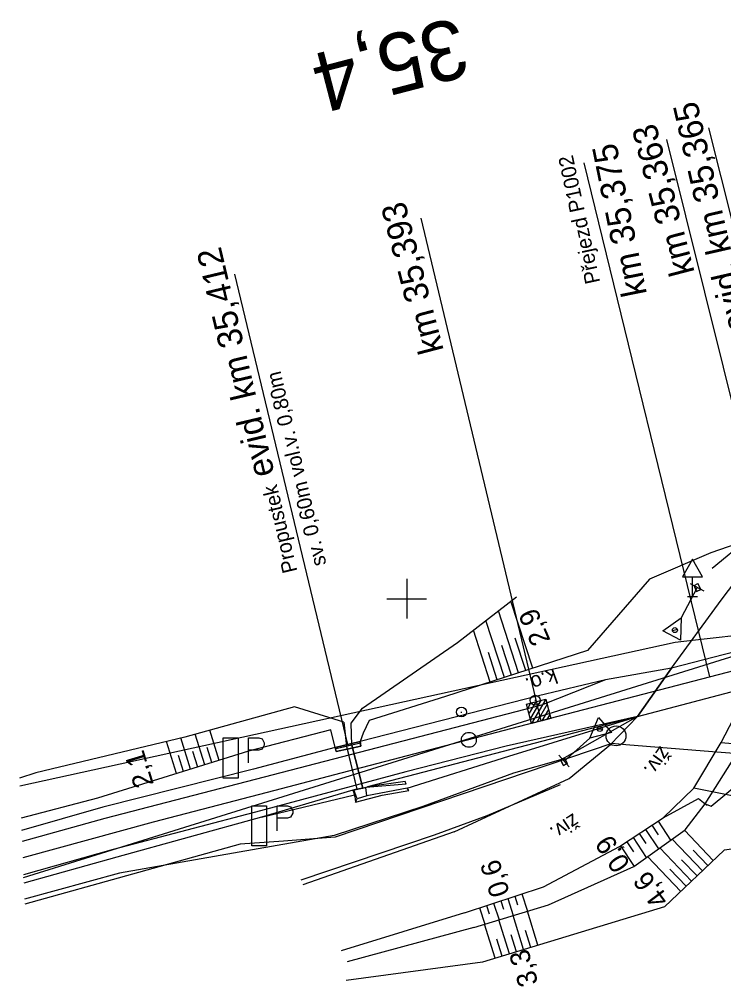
# Model space of a CAD drawing. Extents: x -806456 to -805395, y -1150847 to -1150506.
# Drawn here: x -806239 to -806168.1, y -1150739 to -1150641.7 of the extents above; entities that cross this region are included whole.
import ezdxf

# ---------------------------------------------------------------- set-up
doc = ezdxf.new("R2010")
doc.units = 0
for name, color, linetype in [('0381KM032-037P - Vrstva 1', 7, 'Continuous'), ('0381KM032-037P - Vrstva 12', 7, 'Continuous'), ('0381KM032-037P - Vrstva 13', 7, 'Continuous'), ('0381KM032-037P - Vrstva 16', 7, 'Continuous'), ('0381KM032-037P - Vrstva 17', 7, 'Continuous'), ('0381KM032-037P - Vrstva 19', 7, 'Continuous'), ('0381KM032-037P - Vrstva 27', 7, 'Continuous'), ('0381KM032-037P - Vrstva 3', 7, 'Continuous'), ('0381KM032-037P - Vrstva 36', 7, 'Continuous'), ('0381KM032-037P - Vrstva 4', 7, 'Continuous'), ('0381KM032-037P - Vrstva 43', 7, 'Continuous'), ('0381KM032-037P - Vrstva 48', 7, 'Continuous'), ('0381KM032-037P - Vrstva 49', 7, 'Continuous'), ('0381KM032-037P - Vrstva 51', 7, 'Continuous'), ('0381KM032-037P - Vrstva 7', 7, 'Continuous'), ('hran DP - hran DP', 7, 'Continuous'), ('krizky_1000 - Vrstva 1', 7, 'Continuous'), ('vyt_sit - polygon', 7, 'Continuous')]:
    doc.layers.add(name, color=color, linetype=linetype)

msp = doc.modelspace()

# ---------------------------------------------------------------- linework, layer by layer
at = {"layer": '0381KM032-037P - Vrstva 1'}
for points in [[(-805989.76, -1150661.17), (-806027.03, -1150670.9), (-806064.32, -1150680.56), (-806101.67, -1150690.24), (-806138.44, -1150699.75), (-806158.28, -1150704.94), (-806163.64, -1150706.34), (-806175.38, -1150709.4), (-806186.46, -1150712.29), (-806205.201, -1150717.188), (-806213.26, -1150719.29)], [(-806213.26, -1150719.29), (-806225.487, -1150722.48), (-806238.622, -1150726.073)]]:
    msp.add_lwpolyline(points, dxfattribs=at)
at = {"layer": '0381KM032-037P - Vrstva 12'}
for p, q in [((-806171.097, -1150698.685), (-806170.698, -1150698.477)), ((-806170.424, -1150699.073), (-806170.42, -1150699.072)), ((-806184.517, -1150716.193), (-806184.135, -1150716.013)), ((-806184.236, -1150716.767), (-806184.232, -1150716.767)), ((-806183.852, -1150716.584), (-806183.846, -1150716.582))]:
    msp.add_line(p, q, dxfattribs=at)
for points in [[(-806171.096, -1150698.684), (-806170.697, -1150698.478), (-806170.42, -1150699.072), (-806170.837, -1150699.265), (-806171.096, -1150698.684), (-806171.097, -1150698.685), (-806170.836, -1150699.265), (-806170.837, -1150699.265)], [(-806170.836, -1150699.265), (-806170.424, -1150699.073), (-806170.698, -1150698.477), (-806170.697, -1150698.478)], [(-806184.517, -1150716.196), (-806184.136, -1150716.011), (-806183.846, -1150716.582), (-806184.232, -1150716.767), (-806184.517, -1150716.196), (-806184.517, -1150716.193), (-806184.236, -1150716.767), (-806183.852, -1150716.584), (-806184.135, -1150716.013), (-806184.136, -1150716.011)]]:
    msp.add_lwpolyline(points, dxfattribs=at)
at = {"layer": '0381KM032-037P - Vrstva 13'}
for p, q in [((-806200.065, -1150718.644), (-806204.115, -1150718.971)), ((-806204.115, -1150718.971), (-806203.948, -1150718.928)), ((-806203.996, -1150719.808), (-806204.115, -1150718.971)), ((-806200.148, -1150718.382), (-806203.948, -1150718.928)), ((-806200.065, -1150718.644), (-806200.148, -1150718.382)), ((-806204.985, -1150720.124), (-806205.321, -1150719.23)), ((-806203.996, -1150719.808), (-806204.985, -1150720.124))]:
    msp.add_line(p, q, dxfattribs=at)
for points in [[(-806204.115, -1150718.971), (-806204.42, -1150719.04), (-806205.012, -1150719.152), (-806205.321, -1150719.23)], [(-806205.147, -1150720.463), (-806202.482, -1150719.745), (-806199.79, -1150719.277), (-806199.947, -1150719.038), (-806203.996, -1150719.808)], [(-806205.415, -1150719.241), (-806205.341, -1150719.246), (-806205.321, -1150719.23)], [(-806205.415, -1150719.241), (-806205.331, -1150719.519), (-806205.259, -1150719.74), (-806205.211, -1150719.896), (-806205.18, -1150720.145), (-806205.147, -1150720.463), (-806204.985, -1150720.124)]]:
    msp.add_lwpolyline(points, dxfattribs=at)
at = {"layer": '0381KM032-037P - Vrstva 16'}
msp.add_lwpolyline([(-806166.069, -1150720.047), (-806171.128, -1150719.056), (-806168.37, -1150714.464), (-806166.085, -1150714.657), (-806164.602, -1150713.817)], dxfattribs=at)
at = {"layer": '0381KM032-037P - Vrstva 17'}
msp.add_line((-806191.898, -1150721.811), (-806184.517, -1150718.669), dxfattribs=at)
for points in [[(-806169.284, -1150696.914), (-806165.684, -1150693.969), (-806155.413, -1150686.939), (-806141.029, -1150680.901), (-806121.846, -1150675.136), (-806106.33, -1150670.053), (-806095.392, -1150665.453)], [(-806210.617, -1150728.275), (-806197.196, -1150723.748), (-806191.898, -1150721.811)]]:
    msp.add_lwpolyline(points, dxfattribs=at)
at = {"layer": '0381KM032-037P - Vrstva 19'}
for p, q in [((-806157.446, -1150701.329), (-806169.593, -1150652.631)), ((-806205.929, -1150714.672), (-806217.278, -1150667.349)), ((-806169.987, -1150720.615), (-806157.733, -1150701.3)), ((-806204.679, -1150714.37), (-806207.178, -1150714.973)), ((-806206.05, -1150714.858), (-806207.127, -1150715.107)), ((-806207.086, -1150715.378), (-806207.127, -1150715.107)), ((-806206.05, -1150714.841), (-806205.013, -1150719.154)), ((-806206.05, -1150714.858), (-806205.012, -1150719.152)), ((-806205.518, -1150714.716), (-806205.523, -1150714.718)), ((-806204.418, -1150719.038), (-806205.523, -1150714.718)), ((-806205.518, -1150714.716), (-806204.42, -1150719.04)), ((-806204.606, -1150714.816), (-806204.652, -1150714.519)), ((-806205.013, -1150719.154), (-806204.418, -1150719.038)), ((-806170.188, -1150720.467), (-806169.786, -1150720.763))]:
    msp.add_line(p, q, dxfattribs=at)
for points in [[(-806204.682, -1150714.372), (-806204.679, -1150714.37), (-806204.652, -1150714.519), (-806207.127, -1150715.107), (-806207.178, -1150714.973), (-806207.177, -1150714.974)], [(-806204.682, -1150714.372), (-806204.606, -1150714.816), (-806207.086, -1150715.378), (-806207.177, -1150714.974), (-806204.682, -1150714.372)], [(-806205.523, -1150714.718), (-806206.05, -1150714.841), (-806206.05, -1150714.858)], [(-806204.652, -1150714.519), (-806205.518, -1150714.716)], [(-806205.341, -1150719.246), (-806203.948, -1150718.928)], [(-806204.418, -1150719.038), (-806204.42, -1150719.04), (-806204.115, -1150718.971), (-806203.948, -1150718.928)], [(-806205.012, -1150719.152), (-806205.321, -1150719.23), (-806205.341, -1150719.246)], [(-806205.013, -1150719.154), (-806205.012, -1150719.152)]]:
    msp.add_lwpolyline(points, dxfattribs=at)
at = {"layer": '0381KM032-037P - Vrstva 27'}
msp.add_line((-806187.119, -1150710.216), (-806187.019, -1150710.216), dxfattribs=at)
msp.add_circle((-806187.069, -1150710.216), 0.5, dxfattribs=at)
at = {"layer": '0381KM032-037P - Vrstva 3'}
for p, q in [((-806186.46, -1150712.29), (-806198.557, -1150661.727)), ((-806186.51, -1150710.236), (-806187.561, -1150712.03)), ((-806185.997, -1150710.102), (-806187.428, -1150712.542)), ((-806187.537, -1150710.504), (-806187.829, -1150711.003)), ((-806187.024, -1150710.37), (-806187.695, -1150711.516)), ((-806185.863, -1150710.615), (-806186.915, -1150712.409)), ((-806185.729, -1150711.129), (-806186.401, -1150712.275)), ((-806185.596, -1150711.642), (-806185.888, -1150712.141))]:
    msp.add_line(p, q, dxfattribs=at)
msp.add_lwpolyline([(-806158.28, -1150704.94), (-806161.571, -1150691.159), (-806164.309, -1150692.072), (-806173.835, -1150653.806)], dxfattribs=at)
msp.add_lwpolyline([(-806185.492, -1150712.038), (-806187.428, -1150712.542), (-806187.932, -1150710.607), (-806185.997, -1150710.102)], close=True, dxfattribs=at)
at = {"layer": '0381KM032-037P - Vrstva 36'}
for points in [[(-806218.444, -1150714.003), (-806216.955, -1150714.003), (-806216.955, -1150718.032), (-806218.444, -1150718.032)], [(-806215.575, -1150720.837), (-806214.086, -1150720.837), (-806214.086, -1150724.866), (-806215.575, -1150724.866)]]:
    msp.add_lwpolyline(points, close=True, dxfattribs=at)
for points in [[(-806215.911, -1150716.502), (-806215.911, -1150713.994)], [(-806215.911, -1150713.994), (-806214.868, -1150713.994)], [(-806214.868, -1150713.994), (-806214.552, -1150714.099), (-806214.331, -1150714.505), (-806214.331, -1150714.726), (-806214.552, -1150715.142), (-806214.868, -1150715.232)], [(-806214.868, -1150715.232), (-806215.911, -1150715.232)], [(-806213.042, -1150723.336), (-806213.042, -1150720.828)], [(-806213.042, -1150720.828), (-806211.999, -1150720.828)], [(-806211.999, -1150720.828), (-806211.683, -1150720.933), (-806211.462, -1150721.339), (-806211.462, -1150721.56), (-806211.683, -1150721.976), (-806211.999, -1150722.066)], [(-806211.999, -1150722.066), (-806213.042, -1150722.066)]]:
    msp.add_lwpolyline(points, dxfattribs=at)
at = {"layer": '0381KM032-037P - Vrstva 4'}
for p, q in [((-806169.501, -1150707.868), (-806182.162, -1150656.159)), ((-806170.089, -1150699.232), (-806171.461, -1150698.498)), ((-806172.782, -1150703.087), (-806173.251, -1150703.226)), ((-806176.794, -1150711.837), (-806203.948, -1150718.928)), ((-806180.805, -1150713.083), (-806180.317, -1150713.117)), ((-806184.68, -1150715.748), (-806183.652, -1150716.916))]:
    msp.add_line(p, q, dxfattribs=at)
for points in [[(-806170.775, -1150698.865), (-806172.404, -1150701.937), (-806172.472, -1150704.171), (-806174.24, -1150703.24), (-806172.404, -1150701.937)], [(-806173.358, -1150707), (-806179.992, -1150708.144), (-806186.437, -1150710.716), (-806215.256, -1150718.168), (-806230.349, -1150722.089), (-806238.693, -1150724.411)], [(-806179.992, -1150708.144), (-806186.747, -1150709.759), (-806204.682, -1150714.372)], [(-806176.794, -1150711.837), (-806190.006, -1150714.82), (-806200.085, -1150717.418), (-806214.718, -1150721.345), (-806229.528, -1150725.211), (-806238.55, -1150727.775)], [(-806184.166, -1150716.332), (-806181.562, -1150714.027), (-806180.714, -1150711.959), (-806179.386, -1150713.451), (-806181.562, -1150714.027)], [(-806207.177, -1150714.974), (-806215.394, -1150717.144), (-806230.58, -1150720.973), (-806238.74, -1150723.305)], [(-806207.177, -1150714.974), (-806207.086, -1150715.378), (-806204.606, -1150714.816), (-806204.682, -1150714.372)], [(-806205.415, -1150719.241), (-806205.341, -1150719.246), (-806203.948, -1150718.928)], [(-806205.415, -1150719.241), (-806214.6, -1150721.97), (-806229.14, -1150726.003), (-806238.515, -1150728.599)]]:
    msp.add_lwpolyline(points, dxfattribs=at)
msp.add_lwpolyline([(-806165.452, -1150708.868), (-806162.708, -1150704.236), (-806173.358, -1150707), (-806176.794, -1150711.837)], close=True, dxfattribs=at)
for centre in [(-806173.016, -1150703.155), (-806180.562, -1150713.101)]:
    msp.add_circle(centre, 0.248, dxfattribs=at)
at = {"layer": '0381KM032-037P - Vrstva 43'}
msp.add_circle((-806178.939, -1150713.793), 1, dxfattribs=at)
at = {"layer": '0381KM032-037P - Vrstva 48'}
for p, q in [((-806187.315, -1150706.999), (-806189.508, -1150700.237)), ((-806188.741, -1150707.462), (-806190.768, -1150701.216)), ((-806190.168, -1150707.925), (-806192.027, -1150702.196)), ((-806191.595, -1150708.388), (-806193.286, -1150703.176)), ((-806188.028, -1150707.231), (-806189.083, -1150703.978)), ((-806190.882, -1150708.156), (-806191.769, -1150705.421)), ((-806189.455, -1150707.693), (-806190.426, -1150704.7)), ((-806221.737, -1150717.148), (-806222.714, -1150714.003)), ((-806220.305, -1150716.703), (-806221.263, -1150713.617)), ((-806218.872, -1150716.258), (-806219.816, -1150713.219)), ((-806223.17, -1150717.593), (-806224.176, -1150714.355)), ((-806219.589, -1150716.48), (-806220.064, -1150714.949)), ((-806222.453, -1150717.37), (-806222.949, -1150715.775)), ((-806221.021, -1150716.925), (-806221.504, -1150715.371)), ((-806175.343, -1150722.788), (-806174.706, -1150723.758)), ((-806174.716, -1150722.377), (-806173.459, -1150724.29)), ((-806176.597, -1150723.612), (-806175.943, -1150724.607)), ((-806175.97, -1150723.2), (-806174.679, -1150725.165)), ((-806169.169, -1150726.326), (-806172.068, -1150723.292)), ((-806178.477, -1150724.847), (-806177.119, -1150726.915)), ((-806177.85, -1150724.435), (-806177.18, -1150725.456)), ((-806177.223, -1150724.024), (-806175.899, -1150726.04)), ((-806170.253, -1150727.362), (-806173.299, -1150724.175)), ((-806171.338, -1150728.398), (-806174.53, -1150725.058)), ((-806169.711, -1150726.844), (-806171.197, -1150725.288)), ((-806172.423, -1150729.435), (-806175.761, -1150725.941)), ((-806170.796, -1150727.88), (-806172.355, -1150726.248)), ((-806171.88, -1150728.916), (-806173.513, -1150727.208)), ((-806188.403, -1150729.694), (-806187.84, -1150731.416)), ((-806191.254, -1150730.626), (-806190.708, -1150732.297)), ((-806190.542, -1150730.393), (-806190.266, -1150731.235)), ((-806189.829, -1150730.16), (-806189.274, -1150731.856)), ((-806189.116, -1150729.927), (-806188.836, -1150730.781)), ((-806192.68, -1150731.092), (-806192.142, -1150732.737)), ((-806191.967, -1150730.859), (-806191.696, -1150731.688)), ((-806186.801, -1150734.851), (-806187.855, -1150731.42)), ((-806189.673, -1150735.718), (-806190.723, -1150732.301)), ((-806188.237, -1150735.284), (-806189.289, -1150731.86)), ((-806191.109, -1150736.152), (-806192.156, -1150732.741)), ((-806187.519, -1150735.068), (-806188.045, -1150733.354)), ((-806190.391, -1150735.935), (-806190.915, -1150734.228)), ((-806188.955, -1150735.501), (-806189.48, -1150733.791))]:
    msp.add_line(p, q, dxfattribs=at)
at = {"layer": '0381KM032-037P - Vrstva 49'}
for p, q in [((-806207.177, -1150714.974), (-806207.636, -1150713.191)), ((-806204.393, -1150713.538), (-806204.682, -1150714.372)), ((-806214.6, -1150721.97), (-806205.259, -1150719.74)), ((-806205.211, -1150719.896), (-806205.259, -1150719.74)), ((-806194.182, -1150731.583), (-806206.578, -1150735.414)), ((-806193.249, -1150733.077), (-806205.97, -1150736.518))]:
    msp.add_line(p, q, dxfattribs=at)
for points in [[(-806157.224, -1150688.717), (-806163.106, -1150693.208), (-806169.402, -1150695.384), (-806175.562, -1150698.028), (-806181.812, -1150705.214), (-806196.093, -1150709.847), (-806203.772, -1150712.233), (-806204.393, -1150713.538)], [(-806205.585, -1150712.508), (-806204.437, -1150711.021), (-806194.881, -1150704.417), (-806188.959, -1150699.809)], [(-806206.314, -1150712.425), (-806211.288, -1150710.871), (-806222.32, -1150713.908), (-806237.293, -1150717.516), (-806238.963, -1150718.052)], [(-806176.794, -1150711.837), (-806184.135, -1150716.013), (-806184.517, -1150716.193), (-806189.244, -1150717.541), (-806198.367, -1150720.903), (-806207.279, -1150723.797), (-806228.886, -1150727.595), (-806238.447, -1150730.204)], [(-806205.211, -1150719.896), (-806205.18, -1150720.145), (-806205.147, -1150720.463), (-806202.482, -1150719.745), (-806199.79, -1150719.277), (-806199.947, -1150719.038), (-806189.725, -1150715.834), (-806176.794, -1150711.837)], [(-806207.636, -1150713.191), (-806215.906, -1150715.336), (-806231.117, -1150720.062), (-806238.793, -1150722.055)], [(-806206.314, -1150712.425), (-806206.05, -1150714.858), (-806207.127, -1150715.107), (-806207.178, -1150714.973), (-806207.177, -1150714.974)], [(-806204.682, -1150714.372), (-806204.679, -1150714.37), (-806204.652, -1150714.519), (-806205.518, -1150714.716), (-806205.585, -1150712.508)], [(-806169.987, -1150720.615), (-806169.362, -1150720.879), (-806166.409, -1150718.419)], [(-806193.249, -1150733.077), (-806185.745, -1150730.772), (-806177.154, -1150726.94), (-806171.988, -1150723.234), (-806169.987, -1150720.615)], [(-806174.208, -1150722.043), (-806170.645, -1150720.091), (-806169.987, -1150720.615)], [(-806214.6, -1150721.97), (-806229.14, -1150726.003), (-806238.515, -1150728.599)], [(-806194.182, -1150731.583), (-806186.226, -1150728.982), (-806178.594, -1150724.924), (-806174.208, -1150722.043)], [(-806159.8, -1150724.204), (-806168.067, -1150725.273), (-806174.063, -1150731.002)], [(-806174.063, -1150731.002), (-806192.389, -1150736.539), (-806206.086, -1150738.397)]]:
    msp.add_lwpolyline(points, dxfattribs=at)
at = {"layer": '0381KM032-037P - Vrstva 51'}
for p, q in [((-806171.742, -1150699.79), (-806170.742, -1150699.79)), ((-806195.218, -1150723.443), (-806210.458, -1150728.774)), ((-806194.182, -1150731.583), (-806206.578, -1150735.414))]:
    msp.add_line(p, q, dxfattribs=at)
for points in [[(-806195.218, -1150723.443), (-806183.651, -1150718.077), (-806179.484, -1150714.678), (-806176.794, -1150711.837), (-806173.358, -1150707), (-806168.375, -1150700.145), (-806163.106, -1150693.208), (-806157.224, -1150688.717), (-806150.874, -1150685.207), (-806140.159, -1150681.153)], [(-806194.182, -1150731.583), (-806186.226, -1150728.982), (-806178.594, -1150724.924), (-806174.208, -1150722.043), (-806171.128, -1150719.056), (-806168.37, -1150714.464), (-806165.452, -1150708.868), (-806162.708, -1150704.236), (-806160.94, -1150702.044), (-806159.44, -1150700.497), (-806157.039, -1150698.345), (-806150.424, -1150694.243), (-806141.479, -1150690.749), (-806131.125, -1150687.358), (-806121.483, -1150684.155)], [(-806171.242, -1150699.79), (-806171.242, -1150697.79), (-806170.242, -1150697.79), (-806171.242, -1150696.04), (-806172.242, -1150697.79), (-806171.242, -1150697.79)]]:
    msp.add_lwpolyline(points, dxfattribs=at)
at = {"layer": '0381KM032-037P - Vrstva 7'}
msp.add_line((-806194.541, -1150711.396), (-806194.441, -1150711.396), dxfattribs=at)
for centre, radius in [((-806194.491, -1150711.396), 0.5), ((-806193.746, -1150714.193), 0.75)]:
    msp.add_circle(centre, radius, dxfattribs=at)
at = {"layer": 'hran DP - hran DP'}
for p, q in [((-806170.06, -1150704.04), (-806162.48, -1150703.19)), ((-806238.93, -1150718.822), (-806172.99, -1150704.37)), ((-806172.99, -1150704.37), (-806170.06, -1150704.04)), ((-806179.38, -1150714.57), (-806207.21, -1150723.98)), ((-806177.96, -1150714.69), (-806179.38, -1150714.57)), ((-806169.25, -1150715.39), (-806177.96, -1150714.69)), ((-806167.06, -1150715.57), (-806169.25, -1150715.39)), ((-806216.74, -1150724.69), (-806238.425, -1150730.722)), ((-806212.4, -1150724.39), (-806216.74, -1150724.69)), ((-806207.21, -1150723.98), (-806212.4, -1150724.39))]:
    msp.add_line(p, q, dxfattribs=at)
at = {"layer": 'krizky_1000 - Vrstva 1'}
for points in [[(-806200, -1150698), (-806200, -1150702)], [(-806202, -1150700), (-806198, -1150700)]]:
    msp.add_lwpolyline(points, dxfattribs=at)
at = {"layer": 'vyt_sit - polygon'}
msp.add_line((-806238.539, -1150728.037), (-806134.243, -1150695.522), dxfattribs=at)

# ---------------------------------------------------------------- texts
at = {"layer": '0381KM032-037P - Vrstva 19'}
for s, height, rotation, p in [('evid. km 35,365', 2.5, 102.91118, (-806165.536, -1150672.85)), ('evid. km 35,412', 2.5, 103.36433, (-806213.267, -1150687.448)), ('sv. 0,60m vol.v. 0,80m', 1.5, 103.36433, (-806208.064, -1150696.537)), ('Propustek', 1.5, 103.36433, (-806210.982, -1150697.231))]:
    msp.add_text(s, height=height, rotation=rotation, dxfattribs=at).set_placement(p)
at = {"layer": '0381KM032-037P - Vrstva 27'}
msp.add_text('k.o.', height=1.5, rotation=200, dxfattribs=at).set_placement((-806185.171, -1150706.984))
at = {"layer": '0381KM032-037P - Vrstva 3'}
for s, rotation, p in [('km 35,363', 104.63828, (-806171.02, -1150667.178)), ('km 35,393', 104.61877, (-806196.259, -1150675.023))]:
    msp.add_text(s, height=2.5, rotation=rotation, dxfattribs=at).set_placement(p)
at = {"layer": '0381KM032-037P - Vrstva 4'}
for s, height, rotation, p in [('km 35,375', 2.5, 101.49293, (-806175.824, -1150669.353)), ('Přejezd P1002', 1.5, 102.15535, (-806180.533, -1150668.168))]:
    msp.add_text(s, height=height, rotation=rotation, dxfattribs=at).set_placement(p)
at = {"layer": '0381KM032-037P - Vrstva 48'}
for s, rotation, p in [('2,9', 113.38848, (-806185.505, -1150704.194)), ('2,1', 106.78146, (-806225.421, -1150718.663)), ('0,9', 123.43046, (-806177.439, -1150726.673)), ('0,6', 108.10376, (-806189.601, -1150729.604)), ('4,6', 126.74, (-806173.521, -1150730.195)), ('3,3', 107.07536, (-806186.742, -1150738.651))]:
    msp.add_text(s, height=2, rotation=rotation, dxfattribs=at).set_placement(p)
at = {"layer": '0381KM032-037P - Vrstva 51'}
for rotation, p in [(233.98605, (-806174.484, -1150714.734)), (212.99996, (-806183.234, -1150721.52))]:
    msp.add_text('živ.', height=1.5, rotation=rotation, dxfattribs=at).set_placement(p)
at = {"layer": '0381KM032-037P - Vrstva 7'}
msp.add_text('35,4', height=6, rotation=194.58811, dxfattribs=at).set_placement((-806194.84, -1150641.468))

doc.saveas('drawing.dxf')
